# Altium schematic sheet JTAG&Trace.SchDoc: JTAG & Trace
size A4; DocumentNumber: MB1167; Revision: B.1; SheetNumber: 17; SheetTotal: 17; Project: STM327x6G-EVAL
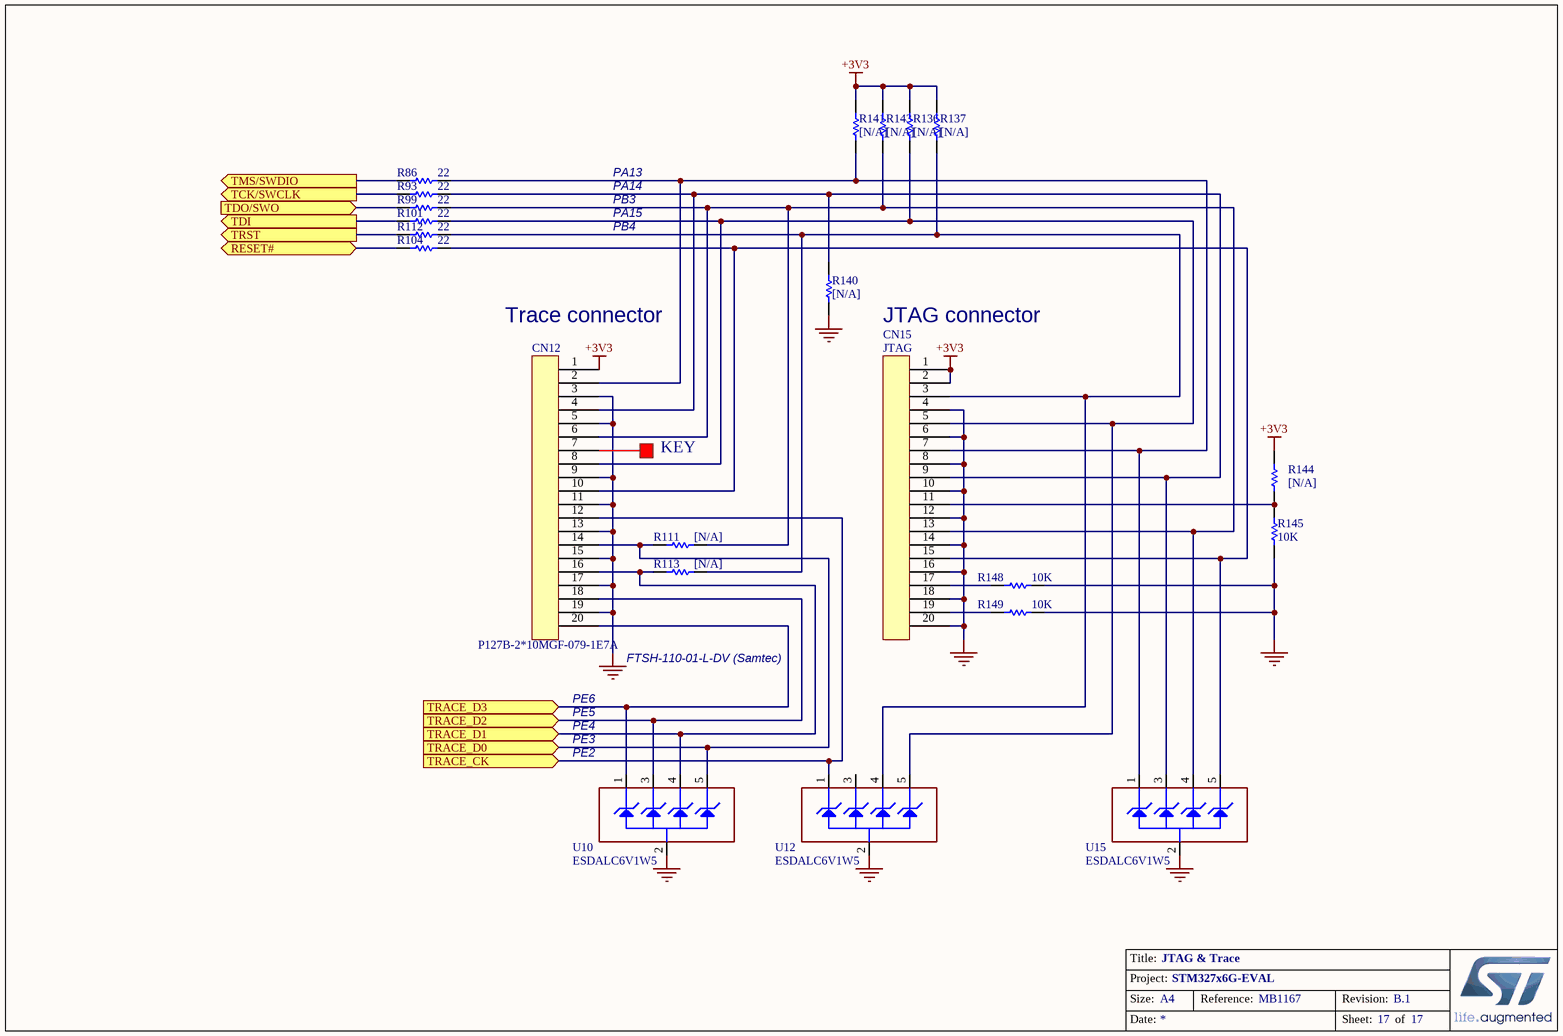
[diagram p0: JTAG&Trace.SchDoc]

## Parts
CN12  P127B-2*10MGF-079-1E7A  [FTSH-110-01-L-DV]
CN15  JTAG  [IDC20S]
R86  22  [0603R]
R93  22  [0603R]
R99  22  [0603R]
R101  22  [0603R]
R104  22  [0603R]
R111  [N/A]  [0603R]
R112  22  [0603R]
R113  [N/A]  [0603R]
R136  [N/A]  [0603R]
R137  [N/A]  [0603R]
R140  [N/A]  [0603R]
R141  [N/A]  [0603R]
R143  [N/A]  [0603R]
R144  [N/A]  [0603R]
R145  10K  [0603R]
R148  10K  [0603R]
R149  10K  [0603R]
U10  ESDALC6V1W5  [SOT-353]
U12  ESDALC6V1W5  [SOT-353]
U15  ESDALC6V1W5  [SOT-353]

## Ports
RESET# (bidir), TCK/SWCLK (out), TDI (out), TDO/SWO (in), TMS/SWDIO (out), TRACE_CK (in), TRACE_D0 (in), TRACE_D1 (in), TRACE_D2 (in), TRACE_D3 (in), TRST (out)

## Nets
+3V3: CN12.1 CN15.1 CN15.2 R136.2 R137.2 R141.2 R143.2 R144.2
GND: CN12.3 CN12.5 CN12.9 CN12.11 CN12.13 CN12.15 CN12.17 CN12.19 CN15.4 CN15.6 CN15.8 CN15.10 CN15.12 CN15.14 CN15.16 CN15.18 CN15.20 R140.1 R145.1 R148.1 R149.1 U10.2(GND) U12.2(GND) U15.2(GND)
RESET#: R104.2 ; port RESET#
TCK/SWCLK: R93.2 ; port TCK/SWCLK
TDI: R101.2 ; port TDI
TDO/SWO: R99.2 ; port TDO/SWO
TMS/SWDIO: R86.2 ; port TMS/SWDIO
TRACE_CK: CN12.12 U12.1(IO1) ; port TRACE_CK
TRACE_D0: CN12.14 R111.1 U10.5(IO4) ; port TRACE_D0
TRACE_D1: CN12.16 R113.1 U10.4(IO3) ; port TRACE_D1
TRACE_D2: CN12.18 U10.3(IO2) ; port TRACE_D2
TRACE_D3: CN12.20 U10.1(IO1) ; port TRACE_D3
TRST: R112.2 ; port TRST
NetCN12_2: CN12.2 CN15.7 R86.1 R141.1 U15.1(IO1)
NetCN12_4: CN12.4 CN15.9 R93.1 R140.2 U15.3(IO2)
NetCN12_6: CN12.6 CN15.13 R99.1 R111.2 R143.1 U15.4(IO3)
NetCN12_8: CN12.8 CN15.5 R101.1 R136.1 U12.5(IO4)
NetCN12_10: CN12.10 CN15.15 R104.1 U15.5(IO4)
NetCN15_3: CN15.3 R112.1 R113.2 R137.1 U12.4(IO3)
NetCN15_11: CN15.11 R144.1 R145.2
NetCN15_17: CN15.17 R148.2
NetCN15_19: CN15.19 R149.2

Not connected (* = marked no-connect by the designer): CN12 7; U12 3(IO2)

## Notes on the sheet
- PA13
- PA14
- PB3
- PA15
- PB4
- (near CN12) Trace connector
- JTAG connector
- KEY
- PE6
- PE5
- (near CN12) FTSH-110-01-L-DV (Samtec)
- PE4
- PE3
- (near U10) PE2

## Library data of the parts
CN12 CN15 = 20PIN1
R86 R93 R99 R101 R104 R111-R113 R136 R137 R140 R141 R143-R145 R148 R149 = Res1: Resistor; Value: 1K
U10 U12 U15 = ESDALC6V1W5: Dual Transil array for ESD protection; Manuf_1: STM; Manuf_Part_1: ESDA5V3L; Ref St: 9179034; Provided: ST; ECCN_US/EU: EAR99/NEC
